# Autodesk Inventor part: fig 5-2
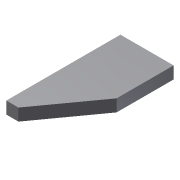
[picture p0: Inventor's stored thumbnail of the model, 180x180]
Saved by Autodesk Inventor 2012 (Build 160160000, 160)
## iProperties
Shininess: 64.0
Length Units: 11272
Angle Units: 11279
Time Units: 11290
Mass Units: 11283
Length Display Precision: 3
Angle Display Precision: 2
Compacted: True
Part Number: fig 5-2
Document SubType Name: Modeling
Created: 2003-01
Designer: Owner
Density: 1 g/cm^3
Material: Default
Density: 0.0
Volumn: 0.0
Area: 0.0
PropertySet Name: Model Information
Control State: 0
Master: False
Checked Out: False
Author: Owner
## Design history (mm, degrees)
sketch "Sketch1"
  geometry: L1 (-795.488, 2648.57)-(-795.488, 3054.97); L2 (1109.512, 1276.97)-(-795.488, 2648.57); L3 (3014.512, 1276.97)-(1109.512, 1276.97); L4 (3014.512, 3054.97)-(3014.512, 1276.97); L5 (-795.488, 3054.97)-(3014.512, 3054.97)
  constraints: 10 end point, 2 horizontal, 2 vertical, 1 other
  dimensions: "d1" = 3810 distance of L1.end L4.start; "d3" = 1778 distance of L4.start L3.start; "d5" = 1905 distance of L3.start L2.start; "d7" = 406.4 distance of L1.start L1.end
extrude "ExtrusionBlind1" new body sketch "Sketch1" distance "d8" = 406.4; taper "d9" = 0 deg
body "Solid1"
other parameters: "d2" = 1778 (derived), "d4" = 1905 (derived), "d6" = 406.4 (derived), "d12" = 0 (derived), "d15" = 635 (derived), "d22" = 889 (derived), "d24" = 812.8 (derived), "d26" = 711.2 (derived), "d28" = 914.4 (derived), "d34" = 812.8 (derived), "d36" = 406.4 (derived)
